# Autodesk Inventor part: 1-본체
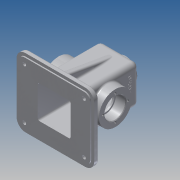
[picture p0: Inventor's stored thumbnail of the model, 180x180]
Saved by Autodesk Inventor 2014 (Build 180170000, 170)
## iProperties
Created: 2015-12
Part Number: 1-본체
Material: 알루미늄 6061
Document SubType Name: Modeling
Designer: Administrator
Mass: 888.312 g
Surface Area: 957.344 cm^2
Volume: 327.79 cm^3
Density: 2.71 g/cm^3
Appearance: 알루미늄 - 평지
Author: Administrator
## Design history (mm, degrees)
sketch "스케치1"
  geometry: L1 (-50, 57.5)-(50, 57.5); L2 (65, 42.5)-(65, -42.5); L3 (50, -57.5)-(-50, -57.5); L4 (-65, -42.5)-(-65, 42.5); L5 (-65, 57.5)-(65, -57.5); L6 (65, 57.5)-(-65, -57.5); A1 r 15 centre (50, -42.5) between (50, -57.5) and (65, -42.5); A2 r 15 centre (-50, -42.5) between (-65, -42.5) and (-50, -57.5); A3 r 15 centre (-50, 42.5) between (-50, 57.5) and (-65, 42.5); A4 r 15 centre (50, 42.5) between (65, 42.5) and (50, 57.5); 1 further point
  constraints: 12 end point, 8 point on circle, 8 point on line, 8 tangent, 4 centre point, 3 equal radius, 2 midpoint, 2 parallel, 1 horizontal, 1 perpendicular
  dimensions: "d0" = 130 distance of L5.end L6.end; "d1" = 115 distance of L6.start L5.end; "d4" = 15 radius of A1
extrude "돌출1" new body sketch "스케치1" distance "d2" = 8; taper "d3" = 0 deg
sketch "스케치2"
  geometry: L1 (-24.5, 32.5)-(24.5, 32.5); L2 (32.5, 24.5)-(32.5, -24.5); L3 (24.5, -32.5)-(-24.5, -32.5); L4 (-32.5, -24.5)-(-32.5, 24.5); L5 (-32.5, 32.5)-(32.5, -32.5); L6 (32.5, 32.5)-(-32.5, -32.5); A1 r 8 centre (-24.5, 24.5) between (-24.5, 32.5) and (-32.5, 24.5); A2 r 8 centre (24.5, 24.5) between (32.5, 24.5) and (24.5, 32.5); A3 r 8 centre (24.5, -24.5) between (24.5, -32.5) and (32.5, -24.5); A4 r 8 centre (-24.5, -24.5) between (-32.5, -24.5) and (-24.5, -32.5); 1 further point
  constraints: 12 end point, 8 point on circle, 8 point on line, 8 tangent, 4 centre point, 3 equal radius, 2 midpoint, 2 parallel, 1 horizontal, 1 perpendicular
  dimensions: "d5" = 65 distance of L5.end L6.end; "d6" = 65 distance of L6.start L5.end; "d7" = 8 radius of A1
extrude "돌출2" join sketch "스케치2" distance "d8" = 100; taper "d9" = 0 deg
sketch "스케치3"
  geometry: L1 (-65, -42.5)-(-65, 42.5) reference; L2 (50, -57.5)-(-50, -57.5) reference; L3 (65, 42.5)-(65, -42.5) reference; L4 (-50, 57.5)-(50, 57.5) reference; L5 (60, 42.5)-(60, -42.5); L6 (50, -52.5)-(-50, -52.5); L7 (-60, -42.5)-(-60, 42.5); L8 (-50, 52.5)-(50, 52.5); A1 r 15 centre (-50, -42.5) between (-65, -42.5) and (-50, -57.5) reference; A2 r 15 centre (50, -42.5) between (50, -57.5) and (65, -42.5) reference; A3 r 15 centre (50, 42.5) between (65, 42.5) and (50, 57.5) reference; A4 r 15 centre (-50, 42.5) between (-50, 57.5) and (-65, 42.5) reference; A5 r 10 centre (50, 42.5) between (60, 42.5) and (50, 52.5); A6 r 10 centre (50, -42.5) between (50, -52.5) and (60, -42.5); A7 r 10 centre (-50, -42.5) between (-60, -42.5) and (-50, -52.5); A8 r 10 centre (-50, 42.5) between (-50, 52.5) and (-60, 42.5); 1 further point
  constraints: 8 end point, 8 point on circle, 4 centre point, 7 other
  dimensions: "d10" = 5 distance between parallel lines of L4 L8
extrude "돌출3" join sketch "스케치3" distance "d11" = 2; taper "d12" = 0 deg
sketch "스케치4"
  geometry: L1 (-18, 0)-(67, 0) reference; L2 (67, -10)-(-18, -10) reference; C1 r 27.5 at (24.5, 45); 2 further points
  constraints: 1 centre point, 1 midpoint, 1 vertical alignment
  dimensions: "d13" = 55 diameter of C1; "d14" = 55 distance from line of L2 C1.centre
extrude "돌출4" join sketch "스케치4" distance "d15" = 15; taper "d16" = 0 deg
feature "쉘1" dims "d17" = 5
sketch "스케치5"
  geometry: L1 (22.5, -23)-(22.5, -72) reference; L2 (74.5, -20)-(25.5, -20) reference; L3 (77.5, -72)-(77.5, -23) reference; L4 (25.5, -75)-(74.5, -75) reference; L5 (105, -5)-(105, -90) reference; L6 (-5, -90)-(-5, -5) reference; L7 (100, -95)-(0, -95) reference; L8 (0, 0)-(100, 0) reference; L9 (22.5, -23)-(22.5, -72) reference; L10 (74.5, -20)-(25.5, -20) reference; L11 (77.5, -72)-(77.5, -23) reference; L12 (25.5, -75)-(74.5, -75) reference; L13 (105, -5)-(105, -90) reference; L14 (0, 0)-(100, 0) reference; L15 (-5, -90)-(-5, -5) reference; L16 (100, -95)-(0, -95) reference; A1 r 3 centre (25.5, -72) between (22.5, -72) and (25.5, -75) reference; A2 r 3 centre (25.5, -23) between (25.5, -20) and (22.5, -23) reference; A3 r 3 centre (74.5, -23) between (77.5, -23) and (74.5, -20) reference; A4 r 3 centre (74.5, -72) between (74.5, -75) and (77.5, -72) reference; A5 r 5 centre (100, -5) between (105, -5) and (100, 0) reference; A6 r 5 centre (0, -5) between (0, 0) and (-5, -5) reference; A7 r 5 centre (0, -90) between (-5, -90) and (0, -95) reference; A8 r 5 centre (100, -90) between (100, -95) and (105, -90) reference; A9 r 3 centre (25.5, -72) between (22.5, -72) and (25.5, -75) reference; A10 r 3 centre (25.5, -23) between (25.5, -20) and (22.5, -23) reference; A11 r 3 centre (74.5, -23) between (77.5, -23) and (74.5, -20) reference; A12 r 3 centre (74.5, -72) between (74.5, -75) and (77.5, -72) reference; A13 r 5 centre (100, -5) between (105, -5) and (100, 0) reference; A14 r 5 centre (0, -5) between (0, 0) and (-5, -5) reference; A15 r 5 centre (0, -90) between (-5, -90) and (0, -95) reference; A16 r 5 centre (100, -90) between (100, -95) and (105, -90) reference; 1 further point
extrude "돌출5" join sketch "스케치5" stored distance "d18" = 15; taper "d19" = 0 deg
sketch "스케치6"
  geometry: C1 r 20 at (0, 0); 1 further point
  constraints: 1 centre point, 1 coincident
  dimensions: "d20" = 40 diameter of C1
extrude "돌출6" join sketch "스케치6" distance "d21" = 10; taper "d22" = -5 deg
sketch "스케치11"
  geometry: C1 r 22.5 at (0, 0) reference; C2 r 27.5 at (0, 0) reference; 1 further point
extrude "돌출9" join sketch "스케치11" stored distance "d71" = 17; taper "d72" = 0 deg
sketch "스케치12"
  geometry: C1 r 27.5 at (0, 0) reference; C2 r 17.5 at (0, 0); 1 further point
  constraints: 1 centre point, 1 coincident
  dimensions: "d73" = 35 diameter of C2
extrude "돌출10" cut sketch "스케치12" distance "d74" = 17; taper "d75" = 0 deg
sketch "스케치13"
  geometry: C1 r 17.5 at (0, 0) reference; C2 r 15 at (0, 0); 1 further point
  constraints: 1 centre point, 1 coincident
  dimensions: "d76" = 30 diameter of C2
extrude "돌출11" cut sketch "스케치13" distance "d77" = 3; taper "d78" = 0 deg
sketch "스케치8"
  geometry: C1 r 19.125 at (0, 0) reference; C2 r 10.5 at (0, 0)
  constraints: 1 centre point, 1 coincident
  dimensions: "d44" = 21 diameter of C2
extrude "돌출7" cut sketch "스케치8" stored distance "d45" = 10; taper "d46" = 0 deg
sketch "스케치9"
  geometry: C1 r 10.5 at (0, 0) reference; 4 further points
  constraints: 1 vertical alignment, 5 other
  dimensions: "d47" = 14.5 distance of C1.centre point (0, 14.5); "d50" = 360 deg dimension on C1.centre point (0, 14.5) (derived)
hole "구멍3" sketch "스케치9" at (0, 14.5), (-14.5, 0), (0, -14.5), (14.5, 0) diameter "d52" = 2.459; stored, may be unused: countersink angle "d56" = 90 deg, drill point angle "d58" = 118 deg; dims "d53" = 7, "d54" = 4, "d55" = 2, "d57" = 9
sketch "스케치14"
  geometry: C1 r 17.5 at (0, 0) reference; 5 further points
  constraints: 1 vertical alignment, 5 other
  dimensions: "d79" = 21 distance of C1.centre point (0, 21); "d82" = 360 deg dimension on C1.centre point (0, 21) (derived)
hole "구멍5" sketch "스케치14" at (0, 21), (-21, 0), (0, -21), (21, 0) diameter "d84" = 3.242; stored, may be unused: countersink angle "d88" = 90 deg, drill point angle "d90" = 118 deg; dims "d85" = 8, "d86" = 4, "d87" = 2, "d89" = 10
sketch "스케치15"
  geometry: L1 (19.125, 118)-(20, 108) reference; L2 (20, 108)-(32.5, 108) reference; L3 (32.5, 108)-(32.5, 80.5) reference; L4 (32.5, 80.5)-(47.5, 80.5) reference; L5 (47.5, 80.5)-(47.5, 75.621) reference; L6 (47.5, 75.621)-(37.5, 75.621) reference; L7 (37.5, 75.621)-(36.526, 74) reference; L8 (37.5, 72.379)-(47.5, 72.379) reference; L9 (47.5, 72.379)-(47.5, 70.5) reference; L10 (47.5, 70.5)-(30.5, 70.5) reference; L11 (30.5, 70.5)-(30.5, 68) reference; L12 (30.5, 68)-(27.5, 68) reference; L13 (27.5, 68)-(27.5, 103) reference; L14 (27.5, 103)-(10.5, 103) reference; L15 (10.5, 103)-(10.5, 118) reference; L16 (10.5, 118)-(13.271, 118) reference; L17 (13.271, 118)-(13.271, 109) reference; L18 (13.271, 109)-(14.5, 108.261) reference; L19 (14.5, 108.261)-(15.73, 109) reference; L20 (15.73, 109)-(15.73, 118) reference; L21 (15.73, 118)-(19.125, 118) reference; L22 (-47.5, 80.5)-(-32.5, 80.5) reference; L23 (-32.5, 80.5)-(-32.5, 108) reference; L24 (-32.5, 108)-(-20, 108) reference; L25 (-20, 108)-(-19.125, 118) reference; L26 (-19.125, 118)-(-15.73, 118) reference; L27 (-15.73, 118)-(-15.73, 109) reference; L28 (-15.73, 109)-(-14.5, 108.261) reference; L29 (-14.5, 108.261)-(-13.271, 109) reference; L30 (-13.271, 109)-(-13.271, 118) reference; L31 (-13.271, 118)-(-10.5, 118) reference; L32 (-10.5, 118)-(-10.5, 103) reference; L33 (-10.5, 103)-(-27.5, 103) reference; L34 (-27.5, 103)-(-27.5, 68) reference; L35 (-27.5, 68)-(-30.5, 68) reference; L36 (-30.5, 68)-(-30.5, 70.5) reference; L37 (-30.5, 70.5)-(-47.5, 70.5) reference; L38 (-47.5, 70.5)-(-47.5, 72.379) reference; L39 (-47.5, 72.379)-(-37.5, 72.379) reference; L40 (-37.5, 72.379)-(-36.526, 74) reference; L41 (-37.5, 75.621)-(-47.5, 75.621) reference; L42 (-47.5, 75.621)-(-47.5, 80.5) reference; L43 (65, 8)-(65, 0) reference; L44 (65, 0)-(60, 0) reference; L45 (60, 0)-(60, -2) reference; L46 (60, -2)-(27.5, -2) reference; L47 (27.5, -2)-(27.5, 38) reference; L48 (27.5, 38)-(30.5, 38) reference; L49 (30.5, 38)-(30.5, 35.5) reference; L50 (30.5, 35.5)-(47.5, 35.5) reference; L51 (47.5, 35.5)-(47.5, 33.621) reference; L52 (47.5, 33.621)-(37.5, 33.621) reference; L53 (37.5, 33.621)-(36.526, 32) reference; L54 (37.5, 30.379)-(47.5, 30.379) reference; L55 (47.5, 30.379)-(47.5, 25.5) reference; L56 (47.5, 25.5)-(32.5, 25.5) reference; L57 (32.5, 25.5)-(32.5, 8) reference; L58 (32.5, 8)-(65, 8) reference; L59 (-65, 0)-(-65, 8) reference; L60 (-65, 8)-(-32.5, 8) reference; L61 (-32.5, 8)-(-32.5, 25.5) reference; L62 (-32.5, 25.5)-(-47.5, 25.5) reference; L63 (-47.5, 25.5)-(-47.5, 30.379) reference; L64 (-47.5, 30.379)-(-37.5, 30.379) reference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; 1 further point
  constraints: 4 end point, 2 midpoint, 2 point on line, 1 parallel, 1 perpendicular
  dimensions: "d91" = 15 distance between parallel lines of L47 L76; "d92" = 15 distance between parallel lines of L75 L71
extrude "돌출12" join sketch "스케치15" stored distance "d93" = 6; taper "d94" = 0 deg
sketch "스케치16"
  geometry: L1 (8, -57.5)-(0, -57.5) reference; L2 (0, -57.5)-(0, -52.5) reference; L3 (0, -52.5)-(-2, -52.5) reference; L4 (-2, -52.5)-(-2, -27.5) reference; L5 (-2, -27.5)-(103, -27.5) reference; L6 (103, -27.5)-(103, -10.5) reference; L7 (103, -10.5)-(118, -10.5) reference; L8 (118, -10.5)-(118, -13.271) reference; L9 (118, -13.271)-(109, -13.271) reference; L10 (109, -13.271)-(108.261, -14.5) reference; L11 (108.261, -14.5)-(109, -15.73) reference; L12 (109, -15.73)-(118, -15.73) reference; L13 (118, -15.73)-(118, -19.125) reference; L14 (118, -19.125)-(108, -20) reference; L15 (108, -20)-(108, -32.5) reference; L16 (108, -32.5)-(8, -32.5) reference; L17 (8, -32.5)-(8, -57.5) reference; L18 (0, 57.5)-(8, 57.5) reference; L19 (8, 57.5)-(8, 32.5) reference; L20 (8, 32.5)-(108, 32.5) reference; L21 (108, 32.5)-(108, 20) reference; L22 (108, 20)-(118, 19.125) reference; L23 (118, 19.125)-(118, 15.73) reference; L24 (118, 15.73)-(109, 15.73) reference; L25 (109, 15.73)-(108.261, 14.5) reference; L26 (108.261, 14.5)-(109, 13.271) reference; L27 (109, 13.271)-(118, 13.271) reference; L28 (118, 13.271)-(118, 10.5) reference; L29 (118, 10.5)-(103, 10.5) reference; L30 (103, 10.5)-(103, 27.5) reference; L31 (103, 27.5)-(-2, 27.5) reference; L32 (-2, 27.5)-(-2, 52.5) reference; L33 (-2, 52.5)-(0, 52.5) reference; L34 (0, 52.5)-(0, 57.5) reference; L35 (8, 47.5)-(93.069, 32.5); L36 (8, -47.5)-(93.069, -32.5); 1 further point
  constraints: 4 end point, 4 point on line
  dimensions: "d95" = 10 deg angle of L35 L18; "d96" = 10 deg angle of L1 L36; "d97" = 10 distance from line of L1 L36.start; "d98" = 10 distance from line of L18 L35.start
extrude "돌출13" join sketch "스케치16" stored distance "d99" = 10; taper "d100" = 0 deg
sketch "스케치17"
  geometry: C1 r 7.5 at (-50, 42.5); C2 r 7.5 at (50, 42.5); C3 r 7.5 at (50, -42.5); C4 r 7.5 at (-50, -42.5); A1 r 15 centre (-50, -42.5) between (-65, -42.5) and (-50, -57.5) reference; A2 r 15 centre (50, -42.5) between (50, -57.5) and (65, -42.5) reference; A3 r 15 centre (50, 42.5) between (65, 42.5) and (50, 57.5) reference; A4 r 15 centre (-50, 42.5) between (-50, 57.5) and (-65, 42.5) reference; 1 further point
  constraints: 4 centre point, 4 coincident
  dimensions: "d101" = 15 diameter of C1; "d102" = 15 diameter of C2; "d103" = 15 diameter of C3; "d104" = 15 diameter of C4
extrude "돌출14" join sketch "스케치17" distance "d105" = 3; taper "d106" = 0 deg
sketch "스케치18"
  geometry: L1 (7.5, 45.5)-(17.5, 45.5) reference; L2 (17.5, 45.5)-(17.5, 67) reference; L3 (25.5, 75)-(45, 75) reference; L4 (45, 75)-(45, 89.471) reference; L5 (45, 89.471)-(55, 89.471) reference; L6 (55, 89.471)-(55, 75) reference; L7 (55, 75)-(74.5, 75) reference; L8 (82.5, 67)-(82.5, 45.5) reference; L9 (82.5, 45.5)-(92.5, 45.5) reference; L10 (92.5, 45.5)-(92.5, 39.5) reference; L11 (92.5, 39.5)-(82.5, 39.5) reference; L12 (82.5, 39.5)-(82.5, 18) reference; L13 (74.5, 10)-(55, 10) reference; L14 (55, 10)-(55, -4.471) reference; L15 (55, -4.471)-(45, -4.471) reference; L16 (45, -4.471)-(45, 10) reference; L17 (45, 10)-(25.5, 10) reference; L18 (17.5, 18)-(17.5, 39.5) reference; L19 (17.5, 39.5)-(7.5, 39.5) reference; L20 (7.5, 39.5)-(7.5, 45.5) reference; L21 (22.5, 67)-(22.5, 18) reference; L22 (25.5, 15)-(74.5, 15) reference; L23 (77.5, 18)-(77.5, 67) reference; L24 (74.5, 70)-(25.5, 70) reference; C1 r 7.5 at (100, 0) reference; C2 r 7.5 at (0, 85) reference; C3 r 7.5 at (100, 85) reference; C4 r 7.5 at (0, 0) reference; C5 r 3 at (0, 85); C6 r 3 at (100, 85); C7 r 3 at (100, 0); C8 r 3 at (0, 0); A1 r 8 centre (25.5, 67) between (25.5, 75) and (17.5, 67) reference; A2 r 8 centre (74.5, 67) between (82.5, 67) and (74.5, 75) reference; A3 r 8 centre (74.5, 18) between (74.5, 10) and (82.5, 18) reference; A4 r 8 centre (25.5, 18) between (17.5, 18) and (25.5, 10) reference; A5 r 3 centre (25.5, 18) between (22.5, 18) and (25.5, 15) reference; A6 r 3 centre (74.5, 18) between (74.5, 15) and (77.5, 18) reference; A7 r 3 centre (74.5, 67) between (77.5, 67) and (74.5, 70) reference; A8 r 3 centre (25.5, 67) between (25.5, 70) and (22.5, 67) reference; 1 further point
  constraints: 4 centre point, 4 coincident
  dimensions: "d107" = 6 diameter of C5; "d108" = 6 diameter of C6; "d109" = 6 diameter of C7; "d110" = 6 diameter of C8
extrude "돌출15" cut sketch "스케치18" stored distance "d111" = 1; taper "d112" = 0 deg
fillet "모깎기1"
fillet "모깎기2"
fillet "모깎기3" dims "d113" = 3
fillet "모깎기4" dims "d114" = 3
fillet "모깎기5" dims "d115" = 3
fillet "모깎기6" dims "d116" = 1
fillet "모깎기7" dims "d117" = 3
fillet "모깎기8" dims "d118" = 8
chamfer "모따기1" distance "d119" = 1; stored, may be unused: second distance "d120" = 2, angle "d121" = 45 deg
chamfer "모따기2" distance "d122" = 1; stored, may be unused: second distance "d123" = 2, angle "d124" = 45 deg
chamfer "모따기3" distance "d125" = 1; stored, may be unused: second distance "d126" = 2, angle "d127" = 45 deg
fillet "모깎기9" dims "d128" = 0.3
fillet "모깎기10" dims "d129" = 3
fillet "모깎기11" dims "d130" = 3
fillet "모깎기12" dims "d131" = 3
fillet "모깎기13" dims "d132" = 3
sketch "스케치19"
  geometry: L1 (5.375, 18)-(43.625, 18) reference; 3 further points
  constraints: 1 midpoint, 1 vertical alignment, 1 other
  dimensions: "d133" = 26 distance from line of point (24.5, -8) L1
feature "엠보싱1" sketch "스케치19" dims "d5" = 65, "d6" = 65, "d7" = 8, "d134" = 0.5, "d135" = 0
fillet "모깎기14" dims "d136" = 3
fillet "모깎기15" dims "d137" = 3
node "솔리드1"
mirror "대칭2"
node "투영된 루프1"
node "투영된 루프2"
node "절단 모서리 투영1"
node "절단 모서리 투영2"
node "절단 모서리 투영3"
